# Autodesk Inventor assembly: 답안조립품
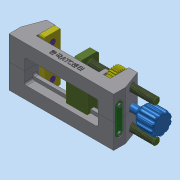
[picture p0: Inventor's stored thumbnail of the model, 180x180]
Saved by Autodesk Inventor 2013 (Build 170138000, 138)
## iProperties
Created: 2017-04
Part Number: 답안조립품
Document SubType Name: Assembly
Designer: dgall
Mass: 1269.82 g
Surface Area: 784.419 cm^2
Volume: 280.831 cm^3
Density: 4.52165 g/cm^3
Author: dgall
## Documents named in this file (10)
- C:\Users\dgall\Desktop\370407V1005\답안조립품.iam
- C:\Users\dgall\Desktop\370407V1005\바이스본체 A.ipt
- C:\Users\dgall\Desktop\370407V1005\바이스본체 B.ipt
- C:\Users\dgall\Desktop\370407V1005\지지대.ipt
- C:\Users\dgall\Desktop\370407V1005\십자오목머리나사 M4.ipt
- C:\Users\dgall\Desktop\370407V1005\고정 플레이트.ipt
- C:\Users\dgall\Desktop\370407V1005\십자오목머리나사 M3.ipt
- C:\Users\dgall\Desktop\370407V1005\슬라이딩 부품.ipt
- C:\Users\dgall\Desktop\370407V1005\핸들.ipt
- C:\Users\dgall\Desktop\370407V1005\스퍼기어.ipt
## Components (3 placed, 2 different names)
1. 고정 플레이트:1
2. 핸들:1
3. 고정 플레이트:2
